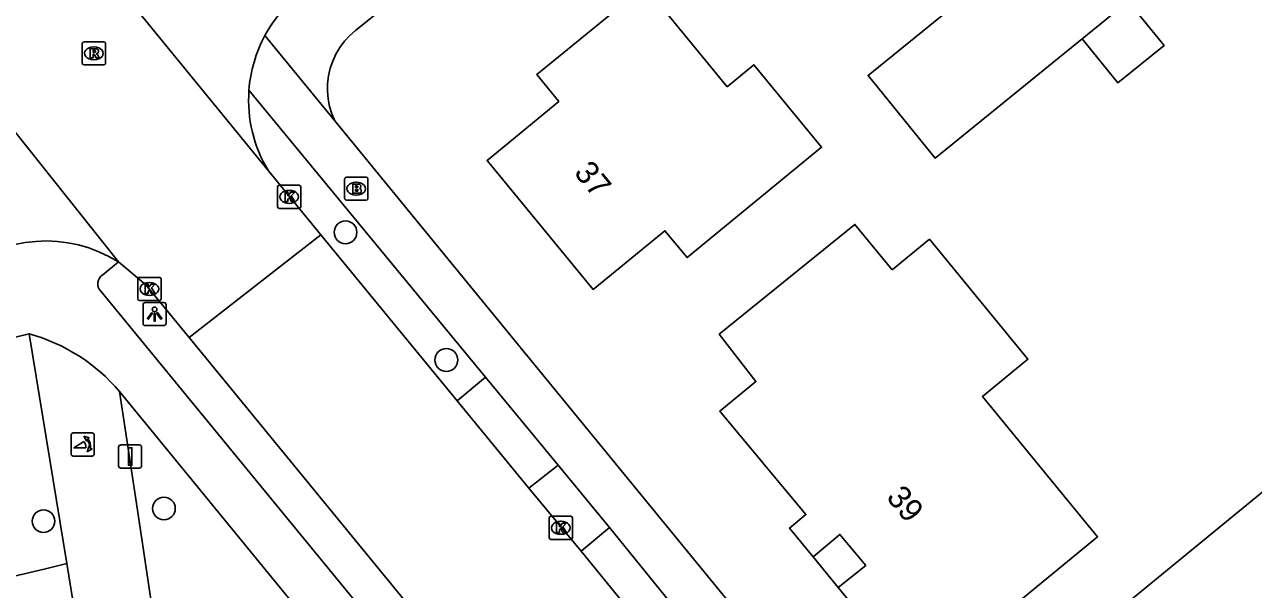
# Model space of a CAD drawing. Extents: x 157321 to 158827, y 386650 to 388532.
# Drawn here: x 157942.8 to 157995.7, y 387325.8 to 387350.1 of the extents above; entities that cross this region are included whole.
import ezdxf

# ---------------------------------------------------------------- set-up
doc = ezdxf.new("R2010")
doc.units = 0
for name, color, linetype in [('IMGEO_Afsluitpaal', 7, 'Continuous'), ('IMGEO_Boom', 7, 'Continuous'), ('IMGEO_Brandkraan', 7, 'Continuous'), ('IMGEO_Fietspad_gesloten', 7, 'Continuous'), ('IMGEO_Groenvoorziening', 7, 'Continuous'), ('IMGEO_Kolk', 7, 'Continuous'), ('IMGEO_Lichtpunt', 7, 'Continuous'), ('IMGEO_Pand', 7, 'Continuous'), ('IMGEO_Pand_nummerreeks', 7, 'Continuous'), ('IMGEO_Pand_overbouw', 7, 'Continuous'), ('IMGEO_Poller', 7, 'Continuous'), ('IMGEO_Rijbaan_lokaal_gesloten', 7, 'Continuous'), ('IMGEO_Rioolput', 7, 'Continuous'), ('IMGEO_Voetpad_open', 7, 'Continuous')]:
    doc.layers.add(name, color=color, linetype=linetype)

msp = doc.modelspace()

# ---------------------------------------------------------------- linework, layer by layer
at = {"layer": 'IMGEO_Afsluitpaal'}
for p, q in [((157946.873, 387331.13), (157946.873, 387331.93)), ((157946.873, 387331.93), (157946.873, 387331.13)), ((157946.973, 387332.03), (157947.763, 387332.03)), ((157947.763, 387332.03), (157946.973, 387332.03)), ((157947.863, 387331.93), (157947.863, 387331.13)), ((157947.863, 387331.13), (157947.863, 387331.93)), ((157947.763, 387331.03), (157946.973, 387331.03)), ((157946.973, 387331.03), (157947.763, 387331.03))]:
    msp.add_line(p, q, dxfattribs=at)
msp.add_lwpolyline([(157947.293, 387331.905), (157947.443, 387331.905), (157947.443, 387331.155), (157947.293, 387331.155), (157947.293, 387331.905)], dxfattribs=at)
for centre, start, end in [((157946.973, 387331.93), 90, 180), ((157946.973, 387331.93), 90, 180), ((157947.763, 387331.93), 0, 90), ((157947.763, 387331.93), 360, 90), ((157946.973, 387331.13), 180, 270), ((157946.973, 387331.13), 180, 270), ((157947.763, 387331.13), 270, 0), ((157947.763, 387331.13), 270, 0)]:
    msp.add_arc(centre, 0.1, start, end, dxfattribs=at)
at = {"layer": 'IMGEO_Boom'}
for centre in [(157956.646, 387341.186), (157960.987, 387335.687), (157948.824, 387329.291), (157943.638, 387328.746)]:
    msp.add_circle(centre, 0.489, dxfattribs=at)
at = {"layer": 'IMGEO_Brandkraan'}
for p, q in [((157956.683, 387343.567), (157957.535, 387343.567)), ((157956.608, 387342.641), (157956.608, 387343.493)), ((157957.096, 387343.347), (157957.121, 387343.347)), ((157957.609, 387343.493), (157957.609, 387342.641)), ((157957.535, 387342.567), (157956.683, 387342.567)), ((157957.119, 387342.787), (157957.094, 387342.787))]:
    msp.add_line(p, q, dxfattribs=at)
for points in [[(157956.683, 387343.567), (157957.535, 387343.567)], [(157956.608, 387342.641), (157956.608, 387343.493)], [(157956.956, 387343.267), (157956.956, 387342.867), (157957.169, 387342.867)], [(157957.187, 387343.267), (157956.956, 387343.267)], [(157957.135, 387343.186), (157957.081, 387343.186), (157957.081, 387343.11)], [(157957.081, 387343.11), (157957.134, 387343.11)], [(157957.143, 387343.034), (157957.081, 387343.034), (157957.081, 387342.953)], [(157957.609, 387343.493), (157957.609, 387342.641)], [(157957.535, 387342.567), (157956.683, 387342.567)], [(157957.081, 387342.953), (157957.143, 387342.953)]]:
    msp.add_lwpolyline(points, dxfattribs=at)
for centre, radius, start, end in [((157956.685, 387343.491), 0.0765, 91.552, 178.448), ((157956.685, 387343.491), 0.0765, 91.552, 178.448), ((157957.533, 387343.491), 0.0765, 1.552, 88.448), ((157957.533, 387343.491), 0.0765, 1.552, 88.448), ((157957.136, 387343.148), 0.0379, 267.8285, 90.9355), ((157957.144, 387342.993), 0.0404, 269.8759, 90.5077), ((157957.191, 387343.122), 0.145, 59.4692, 91.5367), ((157957.216, 387343.169), 0.0922, 285.5137, 58.1501), ((157957.221, 387342.977), 0.105, 301.3115, 78.989), ((157956.685, 387342.643), 0.0765, 181.552, 268.448), ((157956.685, 387342.643), 0.0765, 181.552, 268.448), ((157957.175, 387343.118), 0.251, 268.6676, 293.5347), ((157957.533, 387342.643), 0.0765, 271.552, 358.448), ((157957.533, 387342.643), 0.0765, 271.552, 358.448)]:
    msp.add_arc(centre, radius, start, end, dxfattribs=at)
for centre, major_axis, ratio, start_param, end_param in [((157957.095, 387343.067), (-0.387, 0.002), 0.722429, 4.712389, 7.853982), ((157957.12, 387343.067), (-0.39, 0.002), 0.717154, 1.570796, 4.712389)]:
    msp.add_ellipse(centre, major_axis=major_axis, ratio=ratio, start_param=start_param, end_param=end_param, dxfattribs=at)
at = {"layer": 'IMGEO_Fietspad_gesloten'}
for points in [[(157943.026, 387336.817), (157944.636, 387326.919)], [(157958.825, 387248.538), (157958.71, 387250), (157958.598, 387251.434), (157957.242, 387264.362), (157951.641, 387302.843), (157947.638, 387329.502), (157946.913, 387334.332)], [(157944.636, 387326.919), (157948.59, 387302.603), (157954.197, 387264.013), (157955.766, 387251.171), (157955.818, 387250), (157955.899, 387248.147)]]:
    msp.add_lwpolyline(points, dxfattribs=at)
msp.add_arc((157940.905, 387329.216), 7.891, 40.4121, 74.4055, dxfattribs=at)
at = {"layer": 'IMGEO_Groenvoorziening'}
for points in [[(157985.722, 387373.306), (157959.584, 387351.924), (157957.079, 387349.875), (157956.829, 387349.657), (157956.603, 387349.414), (157956.404, 387349.149), (157956.234, 387348.864), (157956.094, 387348.564), (157955.986, 387348.25), (157955.912, 387347.927), (157955.872, 387347.597), (157955.867, 387347.266), (157955.896, 387346.935), (157955.96, 387346.61), (157956.058, 387346.293), (157956.183, 387345.981)], [(157944.636, 387326.919), (157943.661, 387326.684), (157941.835, 387326.245)]]:
    msp.add_lwpolyline(points, dxfattribs=at)
at = {"layer": 'IMGEO_Kolk'}
for p, q in [((157953.719, 387342.288), (157953.719, 387343.14)), ((157953.794, 387343.214), (157954.646, 387343.214)), ((157954.72, 387343.14), (157954.72, 387342.288)), ((157954.207, 387342.994), (157954.232, 387342.994)), ((157954.646, 387342.214), (157953.794, 387342.214)), ((157954.23, 387342.434), (157954.205, 387342.434)), ((157947.698, 387338.321), (157947.698, 387339.173)), ((157947.773, 387339.247), (157948.625, 387339.247)), ((157948.186, 387339.027), (157948.211, 387339.027)), ((157948.699, 387339.173), (157948.699, 387338.321)), ((157948.625, 387338.247), (157947.773, 387338.247)), ((157948.209, 387338.467), (157948.184, 387338.467)), ((157965.415, 387328.033), (157965.415, 387328.885)), ((157965.49, 387328.959), (157966.342, 387328.959)), ((157965.903, 387328.739), (157965.928, 387328.739)), ((157966.416, 387328.885), (157966.416, 387328.033)), ((157966.342, 387327.959), (157965.49, 387327.959)), ((157965.926, 387328.179), (157965.901, 387328.179))]:
    msp.add_line(p, q, dxfattribs=at)
for points in [[(157953.719, 387342.288), (157953.719, 387343.14)], [(157953.794, 387343.214), (157954.646, 387343.214)], [(157954.72, 387343.14), (157954.72, 387342.288)], [(157954.04, 387342.914), (157954.163, 387342.914), (157954.163, 387342.763), (157954.293, 387342.914), (157954.457, 387342.914), (157954.311, 387342.763), (157954.464, 387342.514), (157954.312, 387342.514), (157954.227, 387342.678), (157954.163, 387342.611), (157954.163, 387342.514), (157954.04, 387342.514), (157954.04, 387342.914)], [(157954.646, 387342.214), (157953.794, 387342.214)], [(157947.698, 387338.321), (157947.698, 387339.173)], [(157947.773, 387339.247), (157948.625, 387339.247)], [(157948.019, 387338.947), (157948.142, 387338.947), (157948.142, 387338.796), (157948.272, 387338.947), (157948.436, 387338.947), (157948.29, 387338.796), (157948.443, 387338.547), (157948.291, 387338.547), (157948.206, 387338.711), (157948.142, 387338.644), (157948.142, 387338.547), (157948.019, 387338.547), (157948.019, 387338.947)], [(157948.699, 387339.173), (157948.699, 387338.321)], [(157948.625, 387338.247), (157947.773, 387338.247)], [(157965.415, 387328.033), (157965.415, 387328.885)], [(157965.49, 387328.959), (157966.342, 387328.959)], [(157966.416, 387328.885), (157966.416, 387328.033)], [(157965.736, 387328.659), (157965.859, 387328.659), (157965.859, 387328.508), (157965.989, 387328.659), (157966.153, 387328.659), (157966.007, 387328.508), (157966.16, 387328.259), (157966.008, 387328.259), (157965.923, 387328.423), (157965.859, 387328.356), (157965.859, 387328.259), (157965.736, 387328.259), (157965.736, 387328.659)], [(157966.342, 387327.959), (157965.49, 387327.959)]]:
    msp.add_lwpolyline(points, dxfattribs=at)
for centre, start, end in [((157953.796, 387343.138), 91.552, 178.448), ((157953.796, 387343.138), 91.552, 178.448), ((157954.644, 387343.138), 1.552, 88.448), ((157954.644, 387343.138), 1.552, 88.448), ((157953.796, 387342.29), 181.552, 268.448), ((157953.796, 387342.29), 181.552, 268.448), ((157954.644, 387342.29), 271.552, 358.448), ((157954.644, 387342.29), 271.552, 358.448), ((157947.775, 387339.171), 91.552, 178.448), ((157947.775, 387339.171), 91.552, 178.448), ((157948.623, 387339.171), 1.552, 88.448), ((157948.623, 387339.171), 1.552, 88.448), ((157947.775, 387338.323), 181.552, 268.448), ((157947.775, 387338.323), 181.552, 268.448), ((157948.623, 387338.323), 271.552, 358.448), ((157948.623, 387338.323), 271.552, 358.448), ((157965.492, 387328.883), 91.552, 178.448), ((157965.492, 387328.883), 91.552, 178.448), ((157966.34, 387328.883), 1.552, 88.448), ((157966.34, 387328.883), 1.552, 88.448), ((157965.492, 387328.035), 181.552, 268.448), ((157965.492, 387328.035), 181.552, 268.448), ((157966.34, 387328.035), 271.552, 358.448), ((157966.34, 387328.035), 271.552, 358.448)]:
    msp.add_arc(centre, 0.0765, start, end, dxfattribs=at)
for centre, major_axis, ratio, start_param, end_param in [((157954.206, 387342.714), (-0.387, 0.002), 0.722429, 4.712389, 7.853982), ((157954.231, 387342.714), (-0.39, 0.002), 0.717154, 1.570796, 4.712389), ((157948.185, 387338.747), (-0.387, 0.002), 0.722429, 4.712389, 7.853982), ((157948.21, 387338.747), (-0.39, 0.002), 0.717154, 1.570796, 4.712389), ((157965.902, 387328.459), (-0.387, 0.002), 0.722429, 4.712389, 7.853982), ((157965.927, 387328.459), (-0.39, 0.002), 0.717154, 1.570796, 4.712389)]:
    msp.add_ellipse(centre, major_axis=major_axis, ratio=ratio, start_param=start_param, end_param=end_param, dxfattribs=at)
at = {"layer": 'IMGEO_Lichtpunt'}
for p, q in [((157947.924, 387338.069), (157947.924, 387337.262)), ((157947.924, 387338.069), (157947.924, 387337.262)), ((157948.826, 387338.164), (157948.018, 387338.164)), ((157948.826, 387338.164), (157948.018, 387338.164)), ((157948.92, 387337.262), (157948.92, 387338.069)), ((157948.92, 387337.262), (157948.92, 387338.069)), ((157948.018, 387337.168), (157948.826, 387337.168)), ((157948.018, 387337.168), (157948.826, 387337.168))]:
    msp.add_line(p, q, dxfattribs=at)
for points in [[(157948.298, 387337.733), (157948.337, 387337.705), (157948.149, 387337.443), (157948.111, 387337.47), (157948.298, 387337.733)], [(157948.51, 387337.705), (157948.548, 387337.732), (157948.735, 387337.47), (157948.696, 387337.442), (157948.51, 387337.705)], [(157948.4, 387337.685), (157948.447, 387337.685), (157948.447, 387337.363), (157948.4, 387337.363), (157948.4, 387337.685)]]:
    msp.add_lwpolyline(points, dxfattribs=at)
msp.add_circle((157948.423, 387337.867), 0.0994, dxfattribs=at)
for centre, start, end in [((157948.018, 387338.069), 90, 180), ((157948.018, 387338.069), 90, 180), ((157948.826, 387338.069), 0, 90), ((157948.826, 387338.069), 0, 90), ((157948.018, 387337.262), 180, 270), ((157948.018, 387337.262), 180, 270), ((157948.826, 387337.262), 270, 0), ((157948.826, 387337.262), 270, 360)]:
    msp.add_arc(centre, 0.0946, start, end, dxfattribs=at)
at = {"layer": 'IMGEO_Pand'}
for points in [[(157988.366, 387349.523), (157982.04, 387344.385), (157979.15, 387347.943), (157987.666, 387354.86), (157990.556, 387351.302), (157990.349, 387351.134)], [(157973.083, 387347.454), (157974.235, 387348.403), (157977.15, 387344.848), (157971.354, 387340.096), (157970.404, 387341.255), (157967.313, 387338.72), (157962.739, 387344.28), (157965.831, 387346.822), (157964.883, 387347.977), (157969.534, 387351.787), (157973.083, 387347.454)], [(157990.349, 387351.134), (157991.896, 387349.23), (157989.913, 387347.619), (157988.366, 387349.523)], [(157990.349, 387351.134), (157988.366, 387349.523)], [(157980.186, 387339.573), (157981.789, 387340.889), (157986.034, 387335.718), (157984.075, 387334.11), (157989.032, 387328.071), (157985.155, 387324.889), (157981.29, 387321.717), (157977.869, 387325.887), (157979.047, 387326.837), (157977.935, 387328.172), (157976.784, 387327.214), (157975.769, 387328.449), (157976.472, 387329.029), (157972.77, 387333.486), (157974.319, 387334.757), (157972.741, 387336.795), (157978.586, 387341.523), (157980.186, 387339.573)], [(157997.61, 387331.215), (158000, 387328.308), (158002.296, 387325.515), (158000, 387323.627), (157997.807, 387321.824), (158000, 387319.157), (158004.288, 387313.941), (158000.729, 387311.02), (158000.161, 387311.713), (158000, 387311.581), (157994.446, 387307.032), (157990.701, 387311.593), (157990.008, 387311.025), (157988.234, 387313.201), (157989.171, 387313.973), (157987.777, 387315.659), (157990.221, 387317.668), (157991.788, 387318.957), (157988.138, 387323.453), (157997.61, 387331.215)]]:
    msp.add_lwpolyline(points, dxfattribs=at)
at = {"layer": 'IMGEO_Pand_overbouw'}
msp.add_lwpolyline([(157977.935, 387328.172), (157976.784, 387327.214), (157977.869, 387325.887), (157979.047, 387326.837)], close=True, dxfattribs=at)
at = {"layer": 'IMGEO_Poller'}
for p, q in [((157944.828, 387332.45), (157944.828, 387331.643)), ((157944.828, 387332.45), (157944.828, 387331.643)), ((157945.73, 387332.545), (157944.922, 387332.545)), ((157945.73, 387332.545), (157944.922, 387332.545)), ((157945.824, 387331.643), (157945.824, 387332.45)), ((157945.824, 387331.643), (157945.824, 387332.45)), ((157944.922, 387331.548), (157945.73, 387331.548)), ((157944.922, 387331.548), (157945.73, 387331.548))]:
    msp.add_line(p, q, dxfattribs=at)
for points in [[(157945.463, 387331.901), (157944.95, 387331.901), (157945.38, 387332.176)], [(157945.507, 387332.274), (157945.495, 387332.201), (157945.37, 387332.406)], [(157945.37, 387332.406), (157945.601, 387332.34), (157945.53, 387332.308)], [(157945.523, 387331.729), (157945.589, 387331.96), (157945.619, 387331.892)], [(157945.655, 387331.865), (157945.727, 387331.854), (157945.523, 387331.729)]]:
    msp.add_lwpolyline(points, dxfattribs=at)
for centre, radius, start, end in [((157944.922, 387332.45), 0.0946, 90, 180), ((157944.922, 387332.45), 0.0946, 90, 180), ((157945.73, 387332.45), 0.0946, 0, 90), ((157945.73, 387332.45), 0.0946, 0, 90), ((157945.135, 387331.951), 0.332, 351.3247, 42.4854), ((157945.149, 387331.961), 0.476, 351.7527, 41.1691), ((157945.149, 387331.961), 0.516, 349.3569, 42.2912), ((157944.922, 387331.643), 0.0946, 180, 270), ((157944.922, 387331.643), 0.0946, 180, 270), ((157945.73, 387331.643), 0.0946, 270, 0), ((157945.73, 387331.643), 0.0946, 270, 0)]:
    msp.add_arc(centre, radius, start, end, dxfattribs=at)
at = {"layer": 'IMGEO_Rijbaan_lokaal_gesloten'}
for points in [[(157953.321, 387343.835), (157943.664, 387355.664)], [(157946.867, 387339.91), (157937.337, 387351.884)], [(157953.321, 387343.835), (157955.584, 387341.078)], [(157955.584, 387341.078), (157949.905, 387336.66)], [(157955.584, 387341.078), (157961.452, 387333.927)], [(157949.905, 387336.66), (157948.052, 387338.921), (157946.867, 387339.91)], [(158001.953, 387273.145), (158000, 387275.528), (157949.905, 387336.66)], [(157964.543, 387330.173), (157961.452, 387333.927)], [(157966.789, 387327.454), (157964.543, 387330.173)], [(157969.875, 387323.659), (157966.789, 387327.454)]]:
    msp.add_lwpolyline(points, dxfattribs=at)
for centre, radius, start, end in [((157958.351, 387346.855), 5.888, 135.3992, 151.5802), ((157958.335, 387346.873), 5.865, 151.6628, 175.7981), ((157958.327, 387346.875), 5.856, 175.8064, 211.2688), ((157943.733, 387334.917), 5.896, 57.8842, 130.3444)]:
    msp.add_arc(centre, radius, start, end, dxfattribs=at)
at = {"layer": 'IMGEO_Rioolput'}
for p, q in [((157945.384, 387349.396), (157946.236, 387349.396)), ((157945.309, 387348.47), (157945.309, 387349.322)), ((157945.797, 387349.176), (157945.822, 387349.176)), ((157946.31, 387349.322), (157946.31, 387348.47)), ((157946.236, 387348.396), (157945.384, 387348.396)), ((157945.82, 387348.616), (157945.795, 387348.616))]:
    msp.add_line(p, q, dxfattribs=at)
for points in [[(157945.384, 387349.396), (157946.236, 387349.396)], [(157945.309, 387348.47), (157945.309, 387349.322)], [(157945.898, 387349.094), (157945.646, 387349.096), (157945.646, 387348.696)], [(157945.646, 387348.696), (157945.77, 387348.696), (157945.77, 387348.858), (157945.781, 387348.858)], [(157945.824, 387349.015), (157945.77, 387349.015), (157945.77, 387348.934)], [(157945.77, 387348.934), (157945.822, 387348.934)], [(157945.828, 387348.829), (157945.899, 387348.696), (157946.039, 387348.696), (157945.974, 387348.822)], [(157946.31, 387349.322), (157946.31, 387348.47)], [(157946.236, 387348.396), (157945.384, 387348.396)]]:
    msp.add_lwpolyline(points, dxfattribs=at)
for centre, radius, start, end in [((157945.386, 387349.32), 0.0765, 91.552, 178.448), ((157945.386, 387349.32), 0.0765, 91.552, 178.448), ((157946.234, 387349.32), 0.0765, 1.552, 88.448), ((157946.234, 387349.32), 0.0765, 1.552, 88.448), ((157945.78, 387348.805), 0.0533, 26.0293, 88.6989), ((157945.806, 387349.123), 0.19, 274.7715, 282.9687), ((157945.83, 387348.919), 0.0964, 77.0061, 93.1865), ((157945.844, 387348.976), 0.0378, 276.6634, 79.6772), ((157945.897, 387348.984), 0.109, 350.3612, 89.416), ((157945.895, 387348.984), 0.112, 277.5842, 350.9817), ((157945.879, 387348.769), 0.108, 29.5134, 73.7905), ((157945.386, 387348.472), 0.0765, 181.552, 268.448), ((157945.386, 387348.472), 0.0765, 181.552, 268.448), ((157946.234, 387348.472), 0.0765, 271.552, 358.448), ((157946.234, 387348.472), 0.0765, 271.552, 358.448)]:
    msp.add_arc(centre, radius, start, end, dxfattribs=at)
for centre, major_axis, ratio, start_param, end_param in [((157945.796, 387348.896), (-0.387, 0.002), 0.722429, 4.712389, 7.853982), ((157945.821, 387348.896), (-0.39, 0.002), 0.717154, 1.570796, 4.712389)]:
    msp.add_ellipse(centre, major_axis=major_axis, ratio=ratio, start_param=start_param, end_param=end_param, dxfattribs=at)
at = {"layer": 'IMGEO_Voetpad_open'}
for points in [[(157956.183, 387345.981), (157953.173, 387349.657)], [(157952.486, 387347.303), (157962.681, 387334.949)], [(157956.183, 387345.981), (157990.647, 387303.891)], [(157946.189, 387339.362), (157946.867, 387339.91)], [(158000.735, 387272.069), (158000, 387272.965), (157946.102, 387338.65)], [(157940.591, 387336.228), (157943.026, 387336.817)], [(157961.452, 387333.927), (157962.681, 387334.949)], [(157962.681, 387334.949), (157965.801, 387331.153)], [(157946.913, 387334.332), (157956.447, 387322.693)], [(157964.543, 387330.173), (157965.801, 387331.153)], [(157965.801, 387331.153), (157968.009, 387328.477)], [(157968.009, 387328.477), (157966.789, 387327.454)], [(157968.009, 387328.477), (157971.093, 387324.678)]]:
    msp.add_lwpolyline(points, dxfattribs=at)
msp.add_arc((157946.432, 387338.971), 0.46, 121.8457, 224.2213, dxfattribs=at)

# ---------------------------------------------------------------- texts
at = {"layer": 'IMGEO_Pand_nummerreeks'}
for s, rotation, p in [('37', 309.4428, (157966.447, 387343.739)), ('39', 309.7929, (157979.898, 387329.753))]:
    msp.add_text(s, height=1, rotation=rotation, dxfattribs=at).set_placement(p)

doc.saveas('drawing.dxf')
